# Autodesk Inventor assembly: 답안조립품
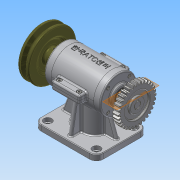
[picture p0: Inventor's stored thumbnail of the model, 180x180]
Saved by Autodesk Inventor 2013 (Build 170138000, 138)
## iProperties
Created: 2015-09
Part Number: 답안조립품
Document SubType Name: Assembly
Designer: Administrator
Author: Administrator
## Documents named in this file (17)
- C:\Users\Administrator\Desktop\350908V1029\답안조립품.iam
- C:\Users\Administrator\Desktop\350908V1029\본체.ipt
- C:\Users\Administrator\Desktop\350908V1029\M3x0.5x8.ipt
- C:\Users\Administrator\Desktop\350908V1029\M4x0.5x14.ipt
- C:\Users\Administrator\Desktop\350908V1029\V-벨트풀리.ipt
- C:\Users\Administrator\Desktop\350908V1029\가변스프링.ipt
- C:\Users\Administrator\Desktop\350908V1029\뒤커버.ipt
- C:\Users\Administrator\Desktop\350908V1029\멈춤나사.ipt
- C:\Users\Administrator\Desktop\350908V1029\베어링 6201.ipt
- C:\Users\Administrator\Desktop\350908V1029\베어링 6202.ipt
- C:\Users\Administrator\Desktop\350908V1029\본체 커버.ipt
- C:\Users\Administrator\Desktop\350908V1029\스퍼기어.ipt
- C:\Users\Administrator\Desktop\350908V1029\슬라이드.ipt
- C:\Users\Administrator\Desktop\350908V1029\앞커버.ipt
- C:\Users\Administrator\Desktop\350908V1029\오일실.ipt
- C:\Users\Administrator\Desktop\350908V1029\키4x4.ipt
- C:\Users\Administrator\Desktop\350908V1029\편심축.ipt
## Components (14 placed, 4 different names)
1. M4x0.5x14:1
2. V-벨트풀리:1 — 플러쉬:2, 각도:1
3. 가변스프링:1
4. M4x0.5x14:2
5. M4x0.5x14:3
6. M4x0.5x14:4
7. M3x0.5x8:1
8. M3x0.5x8:3
9. M3x0.5x8:4
10. M3x0.5x8:5
11. M3x0.5x8:2
12. M3x0.5x8:6
13. M3x0.5x8:7
14. M3x0.5x8:8
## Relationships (2: Flush 1, Angle 1)
- 플러쉬:2 [Flush]: V-벨트풀리:1
- 각도:1 [Angle]: V-벨트풀리:1
